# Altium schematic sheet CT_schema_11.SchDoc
size 147 x 119 mm
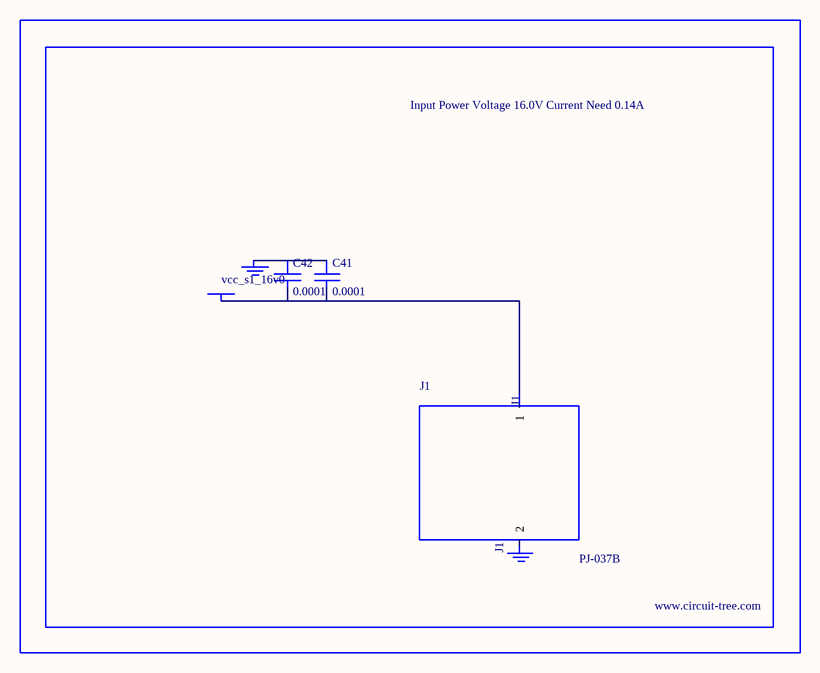
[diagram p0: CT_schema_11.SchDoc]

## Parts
BORDER10  (no value)
C41  0.0001  [EXV-9H]
C42  0.0001  [EXV-9H]
GND_INSTANCE_10_0  (no value)
GND_INSTANCE_10_1  (no value)
J1  PJ-037B  [PJ-037B_PACKAGE]
POWER_INSTANCE_10_0  vcc_s1_16v0

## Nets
NetC41_1: C41.1 C42.1 GND_INSTANCE_10_0.0(GND)
NetC41_2: C41.2 C42.2 J1.1 POWER_INSTANCE_10_0.0(PWR)

Not connected (* = marked no-connect by the designer): GND_INSTANCE_10_1 0(GND); J1 2

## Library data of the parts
BORDER10 = BORDER_PAGE10
C41 C42 = EDK107M035A9HAA
GND_INSTANCE_10_0 GND_INSTANCE_10_1 = GND
POWER_INSTANCE_10_0 = PWR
